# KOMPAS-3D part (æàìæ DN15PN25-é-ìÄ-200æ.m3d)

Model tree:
1. Объединить компоненты:1  (labels: СЕНС DN15PN25-В-НО-200С)

Referenced files in D:\Савин\!СЕНСОР\3D для заказчика\!Новый перечень\СЕНС\7. СЕНС-В-НО-200С\DN15\: СЕНС DN15PN25-В-НО-200С.a3d
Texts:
  СЕНС DN15PN25-В-НО-200С
  ООО НПП Сенсор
